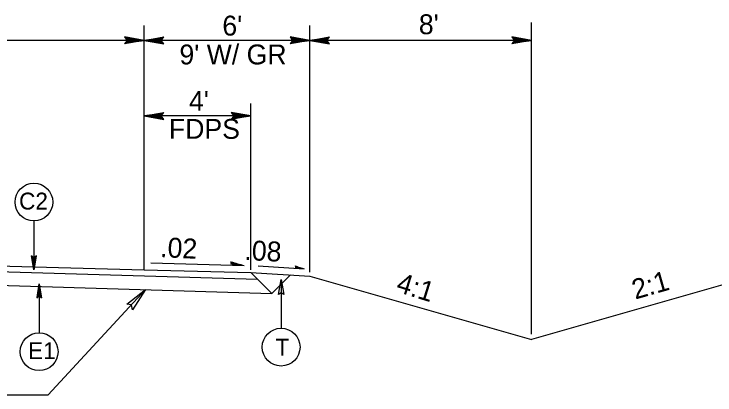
# Model space of a CAD drawing. Extents: x 55823 to 57507, y 47399 to 48499.
# Drawn here: x 56667.6 to 56929.9, y 47896.4 to 48038.9 of the extents above; entities that cross this region are included whole.
import ezdxf

# ---------------------------------------------------------------- set-up
doc = ezdxf.new("R2010")
doc.units = 0
for name, color, linetype in [('Old_Level_1', 7, 'Continuous'), ('Old_Level_11', 7, 'Continuous'), ('Old_Level_2', 7, 'Continuous'), ('Old_Level_20', 7, 'Continuous')]:
    doc.layers.add(name, color=color, linetype=linetype)

msp = doc.modelspace()

# ---------------------------------------------------------------- linework, layer by layer
at = {"layer": 'Old_Level_1'}
for p, q in [((56716.32, 47943.21), (56716.32, 48034.56)), ((56778.32, 47942.3), (56778.32, 48034.56)), ((56861.28, 47919.13), (56861.28, 48035.67)), ((56778.32, 48029.04), (56602.67, 48029.04)), ((56716.34, 48029.02), (56708.97, 48030.32)), ((56708.97, 48030.32), (56709.93, 48029.02)), ((56716.34, 48029.02), (56708.97, 48027.72)), ((56709.93, 48029.02), (56708.97, 48027.72)), ((56709.11, 48030.14), (56716.34, 48029.02)), ((56716.34, 48029.02), (56709.11, 48027.91)), ((56716.34, 48029.02), (56709.25, 48029.95)), ((56709.25, 48028.09), (56716.34, 48029.02)), ((56709.39, 48029.76), (56716.34, 48029.02)), ((56716.34, 48029.02), (56709.39, 48028.28)), ((56716.34, 48029.02), (56709.52, 48029.58)), ((56709.52, 48028.47), (56716.34, 48029.02)), ((56709.66, 48029.39), (56716.34, 48029.02)), ((56716.34, 48029.02), (56709.66, 48028.65)), ((56716.34, 48029.02), (56709.79, 48029.21)), ((56709.79, 48028.84), (56716.34, 48029.02)), ((56709.93, 48029.02), (56716.34, 48029.02)), ((56716.33, 48029.01), (56723.7, 48030.31)), ((56716.33, 48029.01), (56723.56, 48030.13)), ((56723.42, 48029.94), (56716.33, 48029.01)), ((56716.33, 48029.01), (56723.29, 48029.75)), ((56723.15, 48029.57), (56716.33, 48029.01)), ((56716.33, 48029.01), (56723.02, 48029.38)), ((56722.88, 48029.2), (56716.33, 48029.01)), ((56716.33, 48029.01), (56723.7, 48027.71)), ((56723.56, 48027.9), (56716.33, 48029.01)), ((56716.33, 48029.01), (56723.42, 48028.08)), ((56723.29, 48028.27), (56716.33, 48029.01)), ((56716.33, 48029.01), (56723.15, 48028.45)), ((56723.02, 48028.64), (56716.33, 48029.01)), ((56716.33, 48029.01), (56722.88, 48028.82)), ((56722.74, 48029.01), (56716.33, 48029.01)), ((56722.74, 48029.01), (56723.7, 48030.31)), ((56723.7, 48027.71), (56722.74, 48029.01)), ((56778.32, 48029.04), (56770.95, 48030.34)), ((56770.95, 48030.34), (56771.91, 48029.04)), ((56778.32, 48029.04), (56770.95, 48027.74)), ((56771.91, 48029.04), (56770.95, 48027.74)), ((56771.09, 48030.15), (56778.32, 48029.04)), ((56778.32, 48029.04), (56771.09, 48027.92)), ((56778.32, 48029.04), (56771.23, 48029.97)), ((56771.23, 48028.11), (56778.32, 48029.04)), ((56771.37, 48029.78), (56778.32, 48029.04)), ((56778.32, 48029.04), (56771.37, 48028.3)), ((56778.32, 48029.04), (56771.5, 48029.59)), ((56771.5, 48028.48), (56778.32, 48029.04)), ((56771.64, 48029.41), (56778.32, 48029.04)), ((56778.32, 48029.04), (56771.64, 48028.67)), ((56778.32, 48029.04), (56771.77, 48029.23)), ((56771.77, 48028.85), (56778.32, 48029.04)), ((56771.91, 48029.04), (56778.32, 48029.04)), ((56778.32, 48029.04), (56785.69, 48030.34)), ((56778.32, 48029.04), (56785.55, 48030.15)), ((56785.42, 48029.97), (56778.32, 48029.04)), ((56778.32, 48029.04), (56785.28, 48029.78)), ((56785.14, 48029.6), (56778.32, 48029.04)), ((56778.32, 48029.04), (56785.01, 48029.41)), ((56784.87, 48029.23), (56778.32, 48029.04)), ((56778.32, 48029.04), (56785.69, 48027.74)), ((56785.55, 48027.93), (56778.32, 48029.04)), ((56778.32, 48029.04), (56785.42, 48028.11)), ((56785.28, 48028.3), (56778.32, 48029.04)), ((56778.32, 48029.04), (56785.14, 48028.48)), ((56785.01, 48028.67), (56778.32, 48029.04)), ((56778.32, 48029.04), (56784.87, 48028.85)), ((56784.73, 48029.04), (56778.32, 48029.04)), ((56861.28, 48029.04), (56778.32, 48029.04)), ((56784.73, 48029.04), (56785.69, 48030.34)), ((56785.69, 48027.74), (56784.73, 48029.04)), ((56861.28, 48029.04), (56853.91, 48030.34)), ((56853.91, 48030.34), (56854.87, 48029.04)), ((56861.28, 48029.04), (56853.91, 48027.74)), ((56854.87, 48029.04), (56853.91, 48027.74)), ((56854.05, 48030.15), (56861.28, 48029.04)), ((56861.28, 48029.04), (56854.05, 48027.92)), ((56861.28, 48029.04), (56854.19, 48029.97)), ((56854.19, 48028.11), (56861.28, 48029.04)), ((56854.33, 48029.78), (56861.28, 48029.04)), ((56861.28, 48029.04), (56854.33, 48028.3)), ((56861.28, 48029.04), (56854.46, 48029.59)), ((56854.46, 48028.48), (56861.28, 48029.04)), ((56854.6, 48029.41), (56861.28, 48029.04)), ((56861.28, 48029.04), (56854.6, 48028.67)), ((56861.28, 48029.04), (56854.73, 48029.23)), ((56854.73, 48028.85), (56861.28, 48029.04)), ((56854.87, 48029.04), (56861.28, 48029.04)), ((56756.32, 47943.21), (56756.32, 48005.47)), ((56716.32, 48000.75), (56723.69, 48002.05)), ((56716.32, 48000.75), (56723.55, 48001.86)), ((56723.42, 48001.68), (56716.32, 48000.75)), ((56716.32, 48000.75), (56723.28, 48001.49)), ((56723.14, 48001.31), (56716.32, 48000.75)), ((56716.32, 48000.75), (56723.01, 48001.12)), ((56722.87, 48000.94), (56716.32, 48000.75)), ((56756.32, 48000.75), (56716.32, 48000.75)), ((56716.32, 48000.75), (56723.69, 47999.45)), ((56723.55, 47999.64), (56716.32, 48000.75)), ((56716.32, 48000.75), (56723.42, 47999.82)), ((56723.28, 48000.01), (56716.32, 48000.75)), ((56716.32, 48000.75), (56723.14, 48000.19)), ((56723.01, 48000.38), (56716.32, 48000.75)), ((56716.32, 48000.75), (56722.87, 48000.56)), ((56722.73, 48000.75), (56716.32, 48000.75)), ((56722.73, 48000.75), (56723.69, 48002.05)), ((56723.69, 47999.45), (56722.73, 48000.75)), ((56756.32, 48000.75), (56748.95, 48002.05)), ((56748.95, 48002.05), (56749.91, 48000.75)), ((56756.32, 48000.75), (56748.95, 47999.45)), ((56749.91, 48000.75), (56748.95, 47999.45)), ((56749.09, 48001.86), (56756.32, 48000.75)), ((56756.32, 48000.75), (56749.09, 47999.63)), ((56756.32, 48000.75), (56749.23, 48001.68)), ((56749.23, 47999.82), (56756.32, 48000.75)), ((56749.37, 48001.49), (56756.32, 48000.75)), ((56756.32, 48000.75), (56749.37, 48000.01)), ((56756.32, 48000.75), (56749.5, 48001.3)), ((56749.5, 48000.19), (56756.32, 48000.75)), ((56749.64, 48001.12), (56756.32, 48000.75)), ((56756.32, 48000.75), (56749.64, 48000.38)), ((56756.32, 48000.75), (56749.77, 48000.94)), ((56749.77, 48000.56), (56756.32, 48000.75)), ((56749.91, 48000.75), (56756.32, 48000.75)), ((56675.09, 47943.19), (56674.18, 47948.37)), ((56675.09, 47947.7), (56674.18, 47948.37)), ((56675.09, 47943.19), (56674.31, 47948.28)), ((56674.44, 47948.18), (56675.09, 47943.19)), ((56675.09, 47943.19), (56674.57, 47948.08)), ((56674.7, 47947.99), (56675.09, 47943.19)), ((56675.09, 47943.19), (56674.83, 47947.89)), ((56674.96, 47947.8), (56675.09, 47943.19)), ((56675.09, 47943.19), (56676.01, 47948.37)), ((56676.01, 47948.37), (56675.09, 47947.7)), ((56675.88, 47948.28), (56675.09, 47943.19)), ((56675.09, 47943.19), (56675.75, 47948.18)), ((56675.62, 47948.08), (56675.09, 47943.19)), ((56675.09, 47943.19), (56675.48, 47947.99)), ((56675.36, 47947.89), (56675.09, 47943.19)), ((56675.09, 47943.19), (56675.23, 47947.8)), ((56675.09, 47947.7), (56675.09, 47943.19)), ((56602.67, 47946.17), (56716.32, 47943.21)), ((56718.86, 47945.79), (56753.75, 47944.82)), ((56748.87, 47946.1), (56748.91, 47946.06)), ((56748.96, 47946), (56749.03, 47946)), ((56749.01, 47945.87), (56749.49, 47945.88)), ((56749.92, 47945.74), (56749.06, 47945.78)), ((56749.1, 47945.63), (56750.46, 47945.59)), ((56749.1, 47945.5), (56750.99, 47945.43)), ((56749.1, 47945.11), (56752.91, 47944.96)), ((56749.11, 47945.41), (56751.73, 47945.27)), ((56749.11, 47945.31), (56752.05, 47945.17)), ((56749.12, 47945.02), (56753.29, 47944.87)), ((56749.14, 47945.21), (56752.51, 47945.07)), ((56602.67, 47944.33), (56758.78, 47939.72)), ((56716.32, 47943.21), (56756.32, 47942.17)), ((56756.32, 47942.17), (56764.13, 47934.37)), ((56758.97, 47944.72), (56776.25, 47943.59)), ((56773.03, 47944.57), (56773.05, 47944.53)), ((56773.08, 47944.49), (56773.13, 47944.49)), ((56773.11, 47944.4), (56773.43, 47944.4)), ((56773.72, 47944.3), (56773.15, 47944.34)), ((56773.16, 47944.16), (56774.42, 47944.07)), ((56773.16, 47943.9), (56775.69, 47943.7)), ((56773.16, 47943.84), (56775.94, 47943.64)), ((56773.17, 47944.25), (56774.07, 47944.19)), ((56773.17, 47944.1), (56774.91, 47943.94)), ((56773.17, 47944.03), (56775.12, 47943.87)), ((56773.18, 47943.96), (56775.42, 47943.79)), ((56771.06, 47941.29), (56764.13, 47934.37)), ((56602.67, 47939.13), (56764.12, 47934.38)), ((56677.04, 47937.89), (56676.13, 47932.71)), ((56676.26, 47932.81), (56677.04, 47937.89)), ((56677.04, 47937.89), (56676.39, 47932.91)), ((56676.52, 47933), (56677.04, 47937.89)), ((56677.04, 47937.89), (56676.65, 47933.1)), ((56676.78, 47933.19), (56677.04, 47937.89)), ((56677.04, 47937.89), (56676.91, 47933.29)), ((56677.04, 47937.89), (56677.96, 47932.71)), ((56677.04, 47933.39), (56677.04, 47937.89)), ((56677.18, 47933.29), (56677.04, 47937.89)), ((56677.04, 47937.89), (56677.31, 47933.19)), ((56677.44, 47933.1), (56677.04, 47937.89)), ((56677.04, 47937.89), (56677.57, 47933)), ((56677.7, 47932.91), (56677.04, 47937.89)), ((56677.04, 47937.89), (56677.83, 47932.81)), ((56680.41, 47896.36), (56716.84, 47935.77)), ((56676.13, 47932.71), (56677.04, 47933.39)), ((56677.04, 47933.39), (56677.96, 47932.71)), ((56651.17, 47896.36), (56680.41, 47896.36))]:
    msp.add_line(p, q, dxfattribs=at)
for points in [[(56756.32, 47942.17), (56778.32, 47940.85)], [(56778.32, 47940.85), (56861.28, 47917.1)], [(56944.24, 47940.85), (56861.28, 47917.1)]]:
    msp.add_lwpolyline(points, dxfattribs=at)
for centre, radius, start, end in [((56764.93, 47994.81), 51.22, 251.5746, 257.4084), ((56746.37, 47945.17), 2.6, 355.8477, 23.7953), ((56784.95, 47976.61), 34.15, 249.4081, 255.2418), ((56771.34, 47944.01), 1.73, 353.6812, 21.6288)]:
    msp.add_arc(centre, radius, start, end, dxfattribs=at)
at = {"layer": 'Old_Level_11'}
for points in [[(56766.67, 47933.91), (56767.6, 47939.6), (56768.63, 47933.91), (56767.6, 47934.63)], [(56709.81, 47930.38), (56716.84, 47935.77), (56712.02, 47928.27), (56711.64, 47930.14)]]:
    msp.add_lwpolyline(points, close=True, dxfattribs=at)
at = {"layer": 'Old_Level_2'}
for p, q in [((56675.09, 47961.46), (56675.09, 47943.19)), ((56767.6, 47939.6), (56767.6, 47921.33)), ((56677.04, 47937.89), (56677.05, 47919.63))]:
    msp.add_line(p, q, dxfattribs=at)
for centre in [(56675.09, 47968.53), (56767.6, 47914.26), (56677.04, 47912.56)]:
    msp.add_circle(centre, 7.07, dxfattribs=at)

# ---------------------------------------------------------------- texts
at = {"layer": 'Old_Level_1'}
for s, p in [("6'", (56745.61, 48030.83)), ("8'", (56819.14, 48031.33)), ("9' W/ GR", (56729.55, 48020.03)), ("4'", (56733.12, 48002.68)), ('FDPS', (56725.62, 47992.2))]:
    msp.add_text(s, height=7.447, dxfattribs=at).set_placement(p)
for s, rotation, p in [(' .02', 357.1962, (56719.44, 47948.11)), (' .08', 357.1962, (56750.97, 47947.02)), ('2:1', 15.9752, (56900.11, 47932.04)), ('4:1', 342.7093, (56810.26, 47935.14))]:
    msp.add_text(s, height=7.447, rotation=rotation, dxfattribs=at).set_placement(p)
at = {"layer": 'Old_Level_20'}
for s, height, p in [('C2', 6.327, (56669.53, 47965.74)), ('E1', 6.327, (56672.9, 47909.78)), ('T', 6.33, (56765.49, 47911.1))]:
    msp.add_text(s, height=height, dxfattribs=at).set_placement(p)

doc.saveas('drawing.dxf')
